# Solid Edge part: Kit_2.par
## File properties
Sűrűség: 0,000 kg/m^3
Pontosság: 0,990
Author: ahadarics
Last saved by: psaghy
Revision: 78
Username: ahadarics
Dokumentum tartalom típus: 0
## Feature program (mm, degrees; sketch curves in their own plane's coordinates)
base feature "unnamed BaseFeature 1"
sketch for "Furat_1" plane through (0, 0, 39) normal (0, 0, 1) x-axis (0, -1, 0)
  hole centre (-23.25, 23.25) bore radius 3.3235
hole "Furat_1" nominal diameter 8 finite  VBottomAngle = 118 deg
sketch for "unnamed Hole 1" plane through (0, 0, 39) normal (0, 0, 1) x-axis (0, -1, 0)
  hole centre (-23.25, -23.25) bore radius 3.3235
hole "unnamed Hole 1" finite
sketch for "unnamed Hole 2" plane through (0, 0, 39) normal (0, 0, 1) x-axis (0, -1, 0)
  hole centre (23.25, -23.25) bore radius 3.3235
hole "unnamed Hole 2" finite
sketch for "unnamed Hole 3" plane through (0, 0, 39) normal (0, 0, 1) x-axis (0, -1, 0)
  hole centre (23.25, 23.25) bore radius 3.3235
hole "unnamed Hole 3" finite
pattern "unnamed Pattern 1" of "Furat_1", "unnamed Hole 1", "unnamed Hole 2", "unnamed Hole 3"
sketch for "Furat_5" plane through (32.5, 0.0003, 21.2488) normal (1, 0, 0) x-axis (0, 0, -1)
  hole centre (-3.7512, 5.9997) bore radius 5.7225
hole "Furat_5" nominal diameter 13.157 finite  ThreadDepth = 10 mm
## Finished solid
Body 1: solid body, 446 faces, 1036 edges, 651 vertices, 7 internal voids.
  Faces by surface: plane 155, cylinder 135, torus 52, cone 51, sphere 23, spline 21, swept 9
  Edges by curve: line 368, circle 356, curve on surface 286, spline 26
Bounding box of the edges (mm; curved faces can reach further): 65.000 x 65.000 x 56.500, from (-32.5, -32.5, 8) to (32.5002, 32.5, 64.5).
Cylindrical faces by radius (mm): R0.3125 x1, R0.3838 x1, R0.4089 x1, R0.4253 x1, R0.4408 x1, R0.5 x8, R0.5003 x1, R0.5483 x1, R0.5961 x1, R0.615 x1, R0.6311 x1, R0.6362 x1, R0.652 x1, R0.6792 x1, R0.73 x1, R0.7378 x1, R0.7396 x1, R0.9114 x1, R1 x20, R1.0004 x7, R1.001 x6, R1.0014 x8, R1.0015 x1, R1.0026 x1, R1.0394 x1, R1.0539 x1, R1.0734 x1, R1.0987 x1, R1.1871 x1, R1.2561 x1, R1.2722 x2, R1.3621 x1, R1.3711 x1, R1.4 x1, R1.7143 x1, R3.3235 x8, R4 x4, R4.15 x4, R4.5 x1, R5 x2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
Conical faces (half-angle, radius in mm at the cone's reference point): 0.5 deg R18.5 x4, 0.5 deg R22.25 x4, 1.6538 deg R11.75 x1, 3.5477 deg R12.7454 x1, 5.762 deg R10.4 x1, 11.1239 deg R10.0056 x1, 15 deg R18.5156 x1, 15.3654 deg R10.7214 x1, 19.3654 deg R11.1921 x1, 25.0169 deg R14.31 x1, 30 deg R5.1443 x1, 30 deg R11.8557 x2, 30 deg R12.1443 x1, 30 deg R19.5 x1, 31.4296 deg R28.625 x4, 45 deg R2.75 x1, 45 deg R2.825 x1, 45 deg R4.3 x8, 45 deg R6.35 x8, 45 deg R6.72 x1, 45 deg R10.15 x2, 45 deg R15.25 x1, 59 deg R3.3235 x4
Toroidal faces (ring radius, tube radius in mm): R0.4909 r0.5044 x1, R0.5094 r0.5004 x1, R0.8674 r0.5067 x1, R1.4976 r0.5003 x6, R4.3 r0.3 x4, R4.7 r0.3 x1, R6.45 r0.2 x4, R7.15 r0.5 x4, R9.5 r0.5 x1, R9.75 r0.5 x2, R10.3 r0.3 x1, R10.3085 r0.3 x1, R11.4279 r0.25 x1, R12.2464 r0.5 x1, R13.9897 r0.5062 x1, R14.8 r0.2 x1, R17 r2 x1, R17.6163 r0.5 x1, R19.4739 r1 x1, R19.4913 r1 x3, R20.5 r0.5 x1, R21.2587 r1 x3, R21.2761 r1 x1, R27.25 r1 x3, R31.75 r1 x6, R33.3108 r1 x1
Spherical faces by radius (mm): R0.5 x1, R1 x22
Planar faces by outward normal: +x 24, +y 9, +z 36, -x 5, -y 8, -z 24, oblique 49
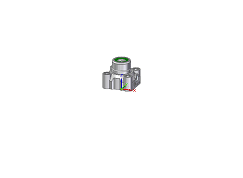
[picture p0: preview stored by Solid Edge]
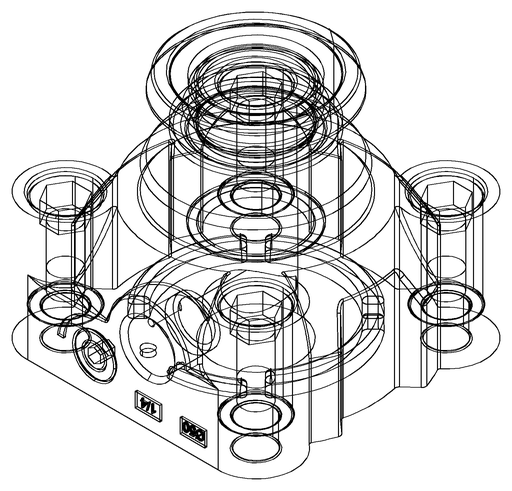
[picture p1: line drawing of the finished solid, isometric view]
